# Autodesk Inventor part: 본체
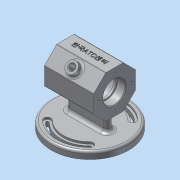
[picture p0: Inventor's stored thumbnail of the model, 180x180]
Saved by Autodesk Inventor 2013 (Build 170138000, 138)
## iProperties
Created: 2017-06
Part Number: 본체
Material: 알루미늄 6061
Document SubType Name: Modeling
Designer: Administrator
Density: 2.71 g/cm^3
Mass: 562.526 g
Surface Area: 565.55 cm^2
Volume: 207.574 cm^3
Author: Administrator
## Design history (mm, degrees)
sketch "스케치1" dims "d0" = 60
  geometry: L1 (30, -12.426)-(12.426, -30); L2 (12.426, -30)-(-12.426, -30); L3 (-12.426, -30)-(-30, -12.426); L4 (-30, -12.426)-(-30, 12.426); L5 (-30, 12.426)-(-12.426, 30); L6 (-12.426, 30)-(12.426, 30); L7 (12.426, 30)-(30, 12.426); L8 (30, 12.426)-(30, -12.426); 5 further points
  constraints: 16 end point, 3 coincident, 2 horizontal alignment, 1 midpoint, 19 other
extrude "돌출1" new body sketch "스케치1" stored distance "d1" = 70; taper "d2" = 0 deg
sketch "스케치2"
  geometry: 1 further point
hole "구멍1" sketch "스케치2" at (0, 0) diameter "d3" = 28; stored, may be unused: countersink angle "d7" = 90 deg, drill point angle "d9" = 118 deg; dims "d4" = 6, "d5" = 4, "d6" = 2, "d8" = 8
hole "구멍2" diameter "d12" = 32; stored, may be unused: countersink angle "d16" = 90 deg, drill point angle "d18" = 0 deg; dims "d10" = 10, "d11" = 10, "d13" = 6, "d14" = 4, "d15" = 2, "d17" = 12
sketch "스케치3"
  geometry: L1 (30, -12.426)-(12.426, -30) reference; L2 (12.426, -30)-(-12.426, -30) reference; L3 (-12.426, -30)-(-30, -12.426) reference; L4 (-30, -12.426)-(-30, 12.426) reference; L5 (-30, 12.426)-(-12.426, 30) reference; L6 (-12.426, 30)-(12.426, 30) reference; L7 (12.426, 30)-(30, 12.426) reference; L8 (30, 12.426)-(30, -12.426) reference; C1 r 25 at (0, 0); C2 r 14 at (0, 0) reference; 1 further point
  constraints: 1 centre point, 1 coincident
  dimensions: "d19" = 50 diameter of C1
extrude "돌출2" cut sketch "스케치3" stored distance "d20" = 40; taper "d21" = 0 deg
node "작업 평면1"
sketch "스케치4"
  geometry: C1 r 55 at (0, 0); 1 further point
  constraints: 1 centre point, 1 coincident
  dimensions: "d23" = 110 diameter of C1
extrude "돌출3" join sketch "스케치4" distance "d24" = 10; taper "d25" = 0 deg
sketch "스케치5"
  geometry: L1 (0, 0)-(33.941, 33.941); L2 (0, 0)-(48, 0); L3 (0, 0)-(-33.941, 33.941); L4 (0, 0)-(48, 0); C1 r 55 at (0, 0) reference; A1 r 43 centre (0, 0) between (30.406, 30.406) and (-30.406, 30.406); A2 r 38 centre (0, 0) between (-26.87, 26.87) and (26.87, 26.87); A3 r 48 centre (0, 0) between (-33.941, 33.941) and (33.941, 33.941); A4 r 5 centre (30.406, 30.406) between (33.73, 26.67) and (33.941, 33.941); A5 r 5 centre (-30.406, 30.406) between (-33.941, 33.941) and (-26.87, 26.87); A6 r 38 centre (0, 0) between (26.87, 26.87) and (-26.87, 26.87); A7 r 48 centre (0, 0) between (33.941, 33.941) and (-33.941, 33.941); A8 r 5 centre (-30.406, 30.406) between (-26.67, 33.73) and (-33.941, 33.941); A9 r 5 centre (-30.406, 30.406) between (-26.87, 26.87) and (-26.67, 33.73); A10 r 5 centre (30.406, 30.406) between (26.87, 26.87) and (33.73, 26.67); A11 r 5 centre (30.406, 30.406) between (33.941, 33.941) and (26.87, 26.87)
  constraints: 26 point on circle, 11 centre point, 8 end point, 3 coincident, 3 point on line, 2 equal length, 2 horizontal, 1 perpendicular
  dimensions: "d26" = 86 diameter of A1; "d27" = 76 diameter of A2; "d28" = 96 diameter of A3; "d30" = 45 deg angle of L2 L1; "d31" = 48 distance of L1.start L3.end; "d32" = 135 deg angle of L4 L3 (derived); "d33" = 10 diameter of A5
extrude "돌출4" cut sketch "스케치5" distance "d34" = 3; taper "d35" = 0 deg
sketch "스케치6"
  geometry: A1 r 38 centre (0, 0) between (26.87, 26.87) and (-26.87, 26.87) reference; A2 r 5 centre (-30.406, 30.406) between (-33.941, 33.941) and (-26.87, 26.87) reference; A3 r 48 centre (0, 0) between (33.941, 33.941) and (-33.941, 33.941) reference; A4 r 5 centre (30.406, 30.406) between (26.87, 26.87) and (33.941, 33.941) reference; A5 r 45 centre (0, 0) between (31.82, 31.82) and (-31.82, 31.82); A6 r 2 centre (-30.406, 30.406) between (-31.82, 31.82) and (-28.991, 28.991); A7 r 41 centre (0, 0) between (28.991, 28.991) and (-28.991, 28.991); A8 r 2 centre (30.406, 30.406) between (28.991, 28.991) and (31.82, 31.82)
  constraints: 8 point on circle, 4 centre point, 3 other
  dimensions: "d38" = 4 radial gap between concentric circles of A7 A5
extrude "돌출5" cut sketch "스케치6" stored distance "d40" = 3; taper "d41" = 0 deg
sketch "스케치7"
  geometry: L1 (-24, 5)-(24, 5); L2 (24, 5)-(24, -5); L3 (24, -5)-(-24, -5); L4 (-24, -5)-(-24, 5); L5 (-24, 5)-(24, -5); L6 (24, 5)-(-24, -5); C1 r 55 at (0, 0) reference; 2 further points
  constraints: 12 end point, 4 midpoint, 2 parallel, 2 vertical alignment, 1 horizontal, 1 perpendicular, 4 other
  dimensions: "d42" = 48 distance of L1.start L1.end; "d44" = 10 distance of L1.end L2.end
extrude "돌출6" join sketch "스케치7" stored distance "d45" = 3; taper "d46" = 0 deg
fillet "모깎기1" dims "d47" = 5
fillet "모깎기2" dims "d48" = 3
fillet "모깎기3" dims "d49" = 0.3
fillet "모깎기4" dims "d50" = 3
sketch "스케치10"
  geometry: L1 (0, 0)-(-37.278, 37.278); L2 (0, 0)-(52.72, 0); L3 (-20.506, 31.82)-(-15.556, 26.87); L4 (-23.335, 28.991)-(-18.385, 24.042); L5 (30, 12.426)-(30, -12.426) reference; L6 (30, -12.426)-(12.426, -30) reference; L7 (12.426, -30)-(-12.426, -30) reference; L8 (-12.426, -30)-(-30, -12.426) reference; L9 (-30, -12.426)-(-30, 12.426) reference; L10 (-30, 12.426)-(-12.426, 30) reference; L11 (-12.426, 30)-(12.426, 30) reference; L12 (12.426, 30)-(30, 12.426) reference; L13 (-30, 12.426)-(-12.426, 30) reference; L14 (-23.335, 28.991)-(-20.506, 31.82); L15 (-15.556, 26.87)-(3.314, 8); L16 (-18.385, 24.042)-(1.687, 3.97); C1 r 16 at (0, 0) reference
  constraints: 14 end point, 2 point on line, 1 equal length, 1 horizontal, 1 parallel
  dimensions: "d51" = 135 deg angle of L2 L1; "d52" = 16 diameter of L3 L1; "d54" = 8 diameter of L4 L1; "d55" = 7 distance between parallel lines of L13 L14
revolve "회전1" sketch "스케치10" stored, may be unused: angle "d56" = 90 deg
sketch "스케치11"
  geometry: C1 r 4 at (0, 0) reference
extrude "돌출7" cut sketch "스케치11" stored distance "d57" = 10; taper "d58" = 0 deg
chamfer "모따기1" distance "d59" = 1; stored, may be unused: second distance "d60" = 2, angle "d61" = 45 deg
fillet "모깎기5" dims "d62" = 1
node "작업 평면2"
sketch "스케치13"
  geometry: L1 (0, -24.024)-(0, 0) reference; L2 (70, 17.988)-(0, 17.988) reference; 2 further points
  constraints: 1 coincident, 1 other
  dimensions: "d64" = 35 distance from line of L1 point (35, -12.012) (derived); "d65" = 30 distance from line of point (35, -12.012) L2 (derived)
feature "엠보싱1" sketch "스케치13" dims "d66" = 0.5, "d67" = 0
sketch "스케치14" dims "d68" = 46
  geometry: C1 r 17 at (0, 0) reference; 2 further points
  constraints: 2 horizontal alignment, 1 coincident, 2 other
hole "구멍3" sketch "스케치14" at (-23, 0) diameter "d69" = 3.242; stored, may be unused: countersink angle "d73" = 90 deg, drill point angle "d75" = 118 deg; dims "d70" = 8, "d71" = 4, "d72" = 2, "d74" = 10
fillet "모깎기6" dims "d79" = 3
node "솔리드1"
mirror "대칭1"
mirror "대칭2"
pattern_circular "원형 패턴1" dims angle "d77" = 360 deg
mirror "대칭3"
node "투영된 루프1"
node "절단 모서리 투영1"
other parameters: "d22" = -62, "d63" = 1
